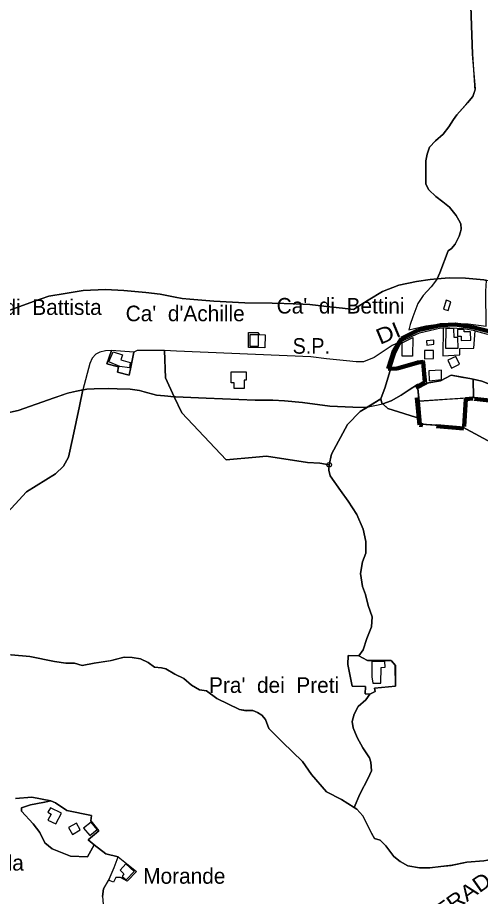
# Model space of a CAD drawing. Extents: x 645880 to 658994, y 884400 to 894744.
# Drawn here: x 655242 to 655748, y 891174 to 892132 of the extents above; entities that cross this region are included whole.
import ezdxf
from ezdxf.enums import TextEntityAlignment as Align

# ---------------------------------------------------------------- set-up
doc = ezdxf.new("R2010")
doc.units = 0
doc.header["$LTSCALE"] = 10
doc.header["$PDMODE"] = 32
doc.header["$PDSIZE"] = 5
doc.linetypes.add('MEDIUM_DASHED', pattern=[4.5, 3, -1.5])
for name, color, linetype, lineweight in [('15', 7, 'MEDIUM_DASHED', 100), ('16', 7, 'Continuous', 25), ('17', 7, 'Continuous', 25), ('2', 7, 'Continuous', 25), ('23', 7, 'Continuous', 25), ('3', 7, 'Continuous', 25), ('30', 7, 'Continuous', 25), ('4', 7, 'Continuous', 25), ('55', 7, 'Continuous', 25), ('6', 7, 'Continuous', 25), ('7', 7, 'Continuous', 25), ('8', 7, 'Continuous', 25)]:
    doc.layers.add(name, color=color, linetype=linetype, lineweight=lineweight)
doc.layers.add('60', color=7, linetype='Continuous')

msp = doc.modelspace()

# ---------------------------------------------------------------- linework, layer by layer
at = {"layer": '15'}
msp.add_lwpolyline([(655646.84, 891749.19), (655653.39, 891769.57), (655661.39, 891782.31), (655679.57, 891791.4), (655703.94, 891796.86), (655720.3, 891797.59), (655740.3, 891794.31), (655765.03, 891788.13), (655784.67, 891779.76), (655812.67, 891765.57), (655817.4, 891761.2), (655803.58, 891742.28), (655790.49, 891748.1), (655785.39, 891736.82), (655770.85, 891713.17), (655739.46, 891716.66), (655731.59, 891716.04), (655729.52, 891684.15), (655680.88, 891688.08), (655676.95, 891728.68), (655687.01, 891734.77), (655685.02, 891756.84), (655679.49, 891755.99), (655656.66, 891749.56)], close=True, dxfattribs=at)
at = {"layer": '16'}
msp.add_line((655300.01, 891217.5), (655279.88, 891225.51), dxfattribs=at)
for points in [[(655719.97, 891885.05), (655724.25, 891894.07), (655725.76, 891898.52), (655726.49, 891901.45), (655726, 891907.49), (655724.13, 891911.49), (655721.15, 891916.55), (655713.8, 891925.74), (655706.51, 891931.31), (655699.02, 891937.11), (655691.32, 891944.32), (655687.8, 891950.52), (655687.83, 891964.63), (655687.99, 891975.96), (655689.38, 891983.24), (655692.1, 891990.88), (655698.55, 891998.12), (655706.76, 892005.17), (655713.02, 892013.38), (655718.06, 892021.09), (655721.68, 892026.19), (655731.7, 892037.05), (655739.31, 892046.15), (655742.28, 892054.6), (655738.97, 892092.57), (655735.1, 892197.24)], [(655700.24, 891847.42), (655703.33, 891853.75), (655712.44, 891877.79), (655715.97, 891880.48), (655719.97, 891885.05)], [(655430.37, 891825.09), (655456.38, 891823.01), (655490.4, 891821.27), (655520.05, 891820.67), (655546.19, 891820.04), (655561.35, 891819.34), (655579.49, 891817.36), (655597.12, 891815.5), (655608.99, 891814.04), (655625.11, 891824.07), (655640.55, 891833.67), (655658.39, 891840.35), (655677.77, 891844.48), (655692.81, 891846.73), (655700.24, 891847.42)], [(655211.7, 891809.51), (655216.33, 891807.57), (655217.29, 891807.64), (655225.68, 891810.38), (655259.64, 891822.71), (655276.25, 891828.39), (655294.18, 891831.5), (655313.72, 891834.83), (655338.39, 891835.61), (655358.19, 891834.55), (655382.34, 891832.59), (655397.87, 891830.69), (655414.28, 891827.27), (655421.79, 891825.76), (655430.37, 891825.09)], [(655313.68, 891726.31), (655306.52, 891724.88), (655296.98, 891722.55), (655282.1, 891717.68), (655262.64, 891710.49), (655243.09, 891703.85), (655222.58, 891699.52), (655203.07, 891700.27), (655188.79, 891704), (655176.07, 891708.49), (655154.59, 891711.51)], [(655297.92, 891652.75), (655302.53, 891674.41), (655309.86, 891708.34), (655313.68, 891726.31)], [(655283.75, 891634.73), (655292.31, 891643.02), (655297.92, 891652.75)], [(655194.14, 891553.82), (655210.59, 891570.1), (655252.01, 891614.96), (655283.75, 891634.73)], [(655391.83, 891423.6), (655384.78, 891428.82), (655376.63, 891432.72), (655367.52, 891434.25), (655358.55, 891434.64), (655343.5, 891430.6), (655325.73, 891428.16), (655312.81, 891425.5), (655304.45, 891428.16), (655294.96, 891428.17), (655282.42, 891429.69), (655255.83, 891435.38), (655235.31, 891437.28), (655214.8, 891435.38), (655193.53, 891432.72), (655174.15, 891432.72), (655164.06, 891433.48)], [(655414.12, 891415.93), (655404.18, 891421.83), (655399.53, 891423), (655391.83, 891423.6)], [(655448.41, 891398), (655440.89, 891398.78), (655432.12, 891404.21), (655423.89, 891411.2), (655414.12, 891415.93)], [(655491.32, 891376.42), (655484.52, 891377.35), (655459.68, 891389.38), (655448.41, 891398)], [(655504.28, 891374.24), (655499.16, 891376.26), (655491.32, 891376.42)], [(655531.34, 891342.01), (655525.92, 891347.38), (655516.69, 891356.69), (655512.89, 891366.48), (655508.86, 891371.37), (655504.28, 891374.24)], [(655579.68, 891287.83), (655563.31, 891306.62), (655553.3, 891320.75), (655531.34, 891342.01)], [(655609.62, 891270.6), (655595.82, 891279.36), (655579.68, 891287.83)], [(655239.85, 891280.32), (655257.81, 891281.71), (655278.73, 891277.92), (655283.76, 891275.63), (655296.11, 891267.39), (655323.1, 891261.67), (655322.41, 891256.18), (655330.87, 891244.96), (655319.21, 891235.35), (655326.07, 891229.86)], [(655270.05, 891275.86), (655278.72, 891277.92), (655257.82, 891281.71), (655239.85, 891280.33)], [(655259.3, 891252.74), (655246.5, 891266.47), (655246.5, 891270.37), (655256.32, 891273.34), (655270.04, 891275.86)], [(655628.81, 891242.58), (655619.19, 891261.38), (655612.5, 891268.62), (655609.62, 891270.6)], [(655279.87, 891225.51), (655272.1, 891232.14), (655266.61, 891243.36), (655259.29, 891252.74)], [(655637.97, 891234.79), (655632.11, 891236.8), (655628.81, 891242.58)], [(655338.47, 891220.11), (655326.07, 891229.86), (655318.75, 891216.81), (655300, 891217.5)], [(655326.07, 891229.86), (655338.47, 891220.11), (655351.99, 891216.87), (655372.17, 891200.77), (655361.89, 891190.13), (655354.57, 891194.25), (655349.54, 891194.25), (655346.89, 891188.94), (655341.73, 891191.31), (655336.12, 891181.8), (655334.94, 891173.54), (655336.12, 891160.58), (655344.36, 891137.59), (655349.67, 891128.75), (655363.8, 891116.96), (655409.75, 891081.01), (655446.27, 891055.66), (655452.99, 891050.47)], [(655652.91, 891217.19), (655644.3, 891228.65), (655637.97, 891234.79)], [(655341.74, 891191.31), (655343.54, 891194.79), (655347.76, 891205.05), (655352, 891216.87), (655338.48, 891220.11)], [(655704.46, 891206.35), (655692.21, 891204.64), (655680.94, 891204.83), (655668.3, 891207.03), (655659.96, 891211.61), (655652.91, 891217.19)], [(655767.1, 891216.28), (655759.41, 891213.88), (655751.17, 891212.3), (655732.6, 891210.97), (655716.83, 891207.52), (655704.46, 891206.35)], [(655334.94, 891173.55), (655336.12, 891181.8), (655341.73, 891191.31)]]:
    msp.add_lwpolyline(points, dxfattribs=at)
at = {"layer": '17'}
msp.add_line((655413.39, 891718.75), (655402.51, 891719.63), dxfattribs=at)
for points in [[(655735.1, 892197.24), (655738.97, 892092.57), (655741.43, 892053.04), (655739.31, 892046.15), (655733.52, 892039.49), (655721.68, 892026.19), (655718.06, 892021.09), (655713.02, 892013.38), (655706.76, 892005.17), (655698.55, 891998.12), (655692.1, 891990.88), (655689.38, 891983.24), (655687.99, 891975.96), (655687.83, 891964.63), (655687.8, 891950.52), (655691.32, 891944.32), (655699.02, 891937.11), (655706.51, 891931.31), (655713.8, 891925.74), (655721.15, 891916.55), (655724.13, 891911.49), (655726, 891907.49), (655726.49, 891901.45), (655725.76, 891898.52), (655724.25, 891894.07), (655719.97, 891885.05)], [(655719.97, 891885.05), (655715.97, 891880.48), (655712.44, 891877.79), (655703.33, 891853.75), (655700.24, 891847.42)], [(655700.24, 891847.42), (655699.56, 891846.42), (655693.7, 891838.71), (655685.03, 891829.36), (655679.08, 891820.43), (655673.63, 891805.75), (655670.94, 891797.41), (655669.46, 891791.77), (655687.95, 891796.1)], [(655687.95, 891796.1), (655704.64, 891798.15), (655718.02, 891798.89), (655734.15, 891798.14), (655753.71, 891795.7), (655753.43, 891833.77), (655754.3, 891845.65)], [(655754.3, 891845.65), (655751.28, 891846.27), (655731.29, 891848.24), (655713.48, 891848.65), (655700.24, 891847.42)], [(655700.24, 891847.42), (655713.48, 891848.65), (655731.29, 891848.24), (655751.28, 891846.27), (655754.3, 891845.65)], [(655332.2, 891767.4), (655327.83, 891765.06), (655323.76, 891760.85)], [(655344.78, 891769.09), (655338.31, 891768.88), (655332.2, 891767.4)], [(655402.54, 891769.12), (655372.88, 891769.05), (655369.38, 891767.53), (655366.07, 891751.07), (655364.09, 891742.17), (655351.2, 891745.67), (655352.51, 891751.29), (655339.9, 891754.79), (655344.78, 891769.09)], [(655365.21, 891726.83), (655375.48, 891725.71), (655380.51, 891724.2), (655394.07, 891720.32), (655402.51, 891719.63), (655413.39, 891718.75), (655403.75, 891739.36), (655402.54, 891769.12)], [(655323.76, 891760.85), (655321.18, 891754.91), (655313.68, 891726.31)], [(655313.68, 891726.31), (655309.86, 891708.34), (655302.53, 891674.41), (655297.92, 891652.75), (655292.31, 891643.02)], [(655313.68, 891726.31), (655317.92, 891727.16), (655325.85, 891727.35), (655341.68, 891727.63), (655350.84, 891727.32), (655365.21, 891726.83)], [(655350.84, 891727.32), (655341.68, 891727.63), (655325.85, 891727.35), (655317.92, 891727.16), (655313.68, 891726.31)], [(655402.51, 891719.63), (655394.07, 891720.32), (655380.51, 891724.2), (655375.48, 891725.71), (655365.21, 891726.83), (655350.84, 891727.32)], [(655626.69, 891394.4), (655621.86, 891394.56), (655622.09, 891402.57), (655607.46, 891402.8), (655602.74, 891426.47), (655603.19, 891436.45), (655614.99, 891436), (655619.73, 891442.67), (655623.59, 891454.9), (655628.74, 891467.78), (655629.38, 891478.72), (655624.88, 891490.95), (655621.98, 891502.86), (655618.76, 891511.87), (655616.83, 891525.71), (655618.76, 891538.59), (655622.3, 891547.92), (655622.62, 891560.8), (655619.73, 891574.32), (655612.65, 891590.41), (655603.32, 891604.9), (655594.96, 891616.49), (655583.7, 891632.26), (655582.09, 891638.7), (655582.42, 891644.49), (655572.43, 891646.12), (655558.88, 891647.07), (655513.97, 891654.03), (655502.53, 891652.82), (655469.89, 891649.98), (655421.64, 891701.11), (655413.39, 891718.75)], [(655682.98, 891688.96), (655682.43, 891694.65), (655646.33, 891705.74), (655640.11, 891711.82), (655638.75, 891716.34), (655616.37, 891702.58), (655602.35, 891688.57), (655585.17, 891656.03)], [(655786.39, 891654.24), (655728.52, 891685.4), (655700.38, 891687.6), (655682.98, 891688.96)], [(655585.17, 891656.03), (655585.17, 891656.03), (655582.42, 891644.49)], [(655292.31, 891643.02), (655283.75, 891634.73), (655252.01, 891614.96)], [(655582.42, 891644.49), (655582.09, 891638.7), (655583.7, 891632.26), (655594.96, 891616.49), (655603.32, 891604.9), (655612.65, 891590.41), (655619.73, 891574.32), (655622.62, 891560.8), (655622.3, 891547.92), (655618.76, 891538.59), (655616.83, 891525.71), (655618.76, 891511.87), (655621.98, 891502.86), (655624.88, 891490.95), (655629.38, 891478.72), (655628.74, 891467.78), (655623.59, 891454.9), (655619.73, 891442.67), (655614.99, 891436)], [(655252.01, 891614.96), (655210.59, 891570.1), (655194.14, 891553.82)], [(655235.32, 891437.29), (655255.83, 891435.39), (655282.42, 891429.69), (655294.96, 891428.17), (655304.46, 891428.17), (655312.81, 891425.5), (655325.73, 891428.17), (655344.34, 891430.83), (655358.55, 891434.64), (655367.52, 891434.25), (655376.63, 891432.72), (655384.78, 891428.82), (655391.83, 891423.6), (655399.53, 891423), (655404.18, 891421.83), (655414.12, 891415.93)], [(655614.99, 891436), (655624.14, 891431.04), (655650.67, 891430.71), (655655.02, 891425.45), (655655.02, 891403.03), (655632.03, 891400.59), (655632.49, 891396.98), (655628.32, 891394.85), (655626.69, 891394.4)], [(655414.12, 891415.93), (655423.89, 891411.2), (655432.12, 891404.21), (655440.89, 891398.78), (655448.41, 891398), (655459.68, 891389.38)], [(655459.68, 891389.38), (655484.52, 891377.35), (655491.97, 891376.1), (655499.16, 891376.26), (655504.28, 891374.24)], [(655609.62, 891270.6), (655615.87, 891285.26), (655624.88, 891302.65), (655628.74, 891310.69), (655628.09, 891320.03), (655626.49, 891324.85), (655619.09, 891335.8), (655612.98, 891347.06), (655608.79, 891357.37), (655607.51, 891364.45), (655609.76, 891372.5), (655614.26, 891380.87), (655622.3, 891387.95), (655626.69, 891394.4)], [(655626.69, 891394.4), (655622.3, 891387.95), (655614.26, 891380.87), (655609.76, 891372.5), (655607.51, 891364.45), (655608.79, 891357.37), (655612.98, 891347.06), (655619.09, 891335.8), (655626.49, 891324.85), (655628.09, 891320.03), (655628.74, 891310.69), (655624.88, 891302.65), (655615.87, 891285.26), (655609.62, 891270.6)], [(655504.28, 891374.24), (655508.86, 891371.37), (655512.89, 891366.48), (655516.69, 891356.69), (655531.34, 891342.01), (655553.3, 891320.75)], [(655553.3, 891320.75), (655563.31, 891306.62), (655579.68, 891287.83)], [(655579.68, 891287.83), (655595.82, 891279.36), (655609.62, 891270.6)], [(655609.62, 891270.6), (655612.5, 891268.62), (655619.19, 891261.38), (655628.81, 891242.58), (655632.11, 891236.8), (655637.97, 891234.79), (655644.3, 891228.65), (655652.91, 891217.19), (655659.96, 891211.61), (655668.3, 891207.03), (655680.94, 891204.83)], [(655680.94, 891204.83), (655692.21, 891204.64), (655704.46, 891206.35), (655715.79, 891207.43), (655732.6, 891210.97), (655751.18, 891212.3), (655759.41, 891213.88)]]:
    msp.add_lwpolyline(points, dxfattribs=at)
msp.add_point((655582.42, 891644.49), dxfattribs=at)
at = {"layer": '2'}
for points in [[(655346.72, 891767.62), (655356.68, 891764.44), (655355.16, 891758.9), (655365.26, 891756.27), (655364.57, 891750.32), (655353.92, 891751.85), (655342.02, 891756.69)], [(655259.29, 891252.74), (655266.61, 891243.36), (655272.1, 891232.14), (655279.87, 891225.51), (655300, 891217.5), (655318.75, 891216.81), (655326.07, 891229.86), (655319.21, 891235.35), (655330.87, 891244.96), (655322.41, 891256.18), (655323.1, 891261.67), (655296.11, 891267.39), (655283.76, 891275.63), (655278.73, 891277.92), (655270.04, 891275.86), (655256.32, 891273.34), (655246.49, 891270.37), (655246.49, 891266.47)], [(655278.11, 891270.03), (655275.42, 891265.54), (655279, 891263.15), (655275.42, 891256.57), (655284.18, 891252.86), (655290.3, 891264.21)], [(655314.08, 891248.17), (655321.11, 891240.01), (655329.26, 891246.56), (655322.5, 891254.71)], [(655297.86, 891248.78), (655302.08, 891241.21), (655310.66, 891246.03), (655306.74, 891253.58)]]:
    msp.add_lwpolyline(points, close=True, dxfattribs=at)
at = {"layer": '23'}
msp.add_lwpolyline([(655680.56, 891714.07), (655682.98, 891688.96), (655728.52, 891685.4), (655730.87, 891717.2)], close=True, dxfattribs=at)
at = {"layer": '3'}
for points in [[(655602.74, 891426.47), (655607.46, 891402.8), (655622.09, 891402.57), (655621.86, 891394.56), (655626.69, 891394.4), (655628.32, 891394.85), (655632.49, 891396.98), (655632.03, 891400.59), (655654.99, 891403.07), (655654.47, 891425.7), (655650.12, 891430.96), (655623.59, 891431.29), (655614.99, 891436), (655603.19, 891436.45)], [(655629.07, 891429.96), (655629.15, 891413.04), (655629.98, 891406.28), (655638.79, 891406.16), (655639.38, 891423.45), (655643.55, 891423.56), (655643.3, 891429.96)]]:
    msp.add_lwpolyline(points, close=True, dxfattribs=at)
at = {"layer": '30'}
msp.add_line((655640.98, 891710.97), (655641.05, 891711.03), dxfattribs=at)
for points in [[(655624.23, 891707.41), (655638.75, 891716.34), (655643.58, 891729.3), (655649.69, 891749.91), (655649.69, 891749.91), (655654.92, 891765.7), (655659.31, 891774.47), (655662.32, 891779.79), (655651.25, 891774.53), (655631.73, 891761.54), (655620.08, 891756.78), (655611.93, 891756.78), (655601.23, 891757.96), (655579.7, 891760.18), (655562.48, 891762.4), (655415.63, 891768.33), (655402.54, 891769.12), (655403.75, 891739.36), (655413.39, 891718.75)], [(655689.09, 891733.72), (655686.48, 891757.95), (655678.39, 891757.37), (655671.21, 891754.75), (655659.82, 891751.55), (655649.69, 891749.91), (655643.58, 891729.3), (655638.75, 891716.34), (655640.11, 891711.82), (655640.98, 891710.97), (655641.05, 891711.03)], [(655689.18, 891732.93), (655686.48, 891757.95), (655678.39, 891757.37), (655671.21, 891754.75), (655659.82, 891751.55), (655649.69, 891749.91), (655643.58, 891729.3), (655638.75, 891716.34), (655640.11, 891711.82), (655640.98, 891710.97), (655641.05, 891711.03)], [(655689.18, 891732.93), (655686.48, 891757.95), (655678.39, 891757.37), (655671.21, 891754.75), (655659.82, 891751.55), (655649.69, 891749.91), (655643.58, 891729.3), (655638.75, 891716.34), (655640.11, 891711.82), (655640.98, 891710.97), (655641.05, 891711.03)], [(655689.18, 891732.93), (655686.48, 891757.95), (655678.39, 891757.37), (655671.21, 891754.75), (655659.82, 891751.55), (655649.69, 891749.91), (655643.58, 891729.3), (655638.75, 891716.34), (655640.11, 891711.82), (655640.98, 891710.97)], [(655669.78, 891726.16), (655678.74, 891732.21), (655689.09, 891733.72)], [(655641.05, 891711.03), (655650.1, 891714.15), (655660.98, 891720.45), (655669.78, 891726.16)], [(655641.05, 891711.03), (655650.1, 891714.15), (655660.98, 891720.45), (655669.78, 891726.16)], [(655641.05, 891711.03), (655650.1, 891714.15), (655660.98, 891720.45), (655669.78, 891726.16)], [(655641.05, 891711.03), (655650.1, 891714.15), (655660.98, 891720.45), (655669.78, 891726.16)], [(655669.78, 891726.16), (655660.98, 891720.45), (655650.1, 891714.15), (655641.05, 891711.03)], [(655669.78, 891726.16), (655678.74, 891732.21), (655689.18, 891732.93)], [(655669.78, 891726.16), (655678.74, 891732.21), (655689.18, 891732.93)], [(655669.78, 891726.16), (655678.74, 891732.21), (655689.18, 891732.93)], [(655689.18, 891732.93), (655678.74, 891732.21), (655669.78, 891726.16)], [(655682.43, 891694.65), (655679.25, 891727.7), (655689.18, 891732.88)], [(655413.39, 891718.75), (655414.72, 891718.64), (655448.2, 891717.07), (655501.55, 891714.9), (655520.78, 891714.9), (655533.84, 891714.12), (655553.45, 891712.46), (655583.07, 891708.37), (655608.33, 891707.35), (655621.67, 891706.86), (655624.23, 891707.41)], [(655624.23, 891707.41), (655621.67, 891706.86), (655608.33, 891707.35), (655583.07, 891708.37), (655553.45, 891712.46), (655533.84, 891714.12), (655520.78, 891714.9), (655501.55, 891714.9), (655448.2, 891717.07), (655414.72, 891718.64), (655413.39, 891718.75)], [(655413.39, 891718.75), (655421.64, 891701.11), (655469.89, 891649.98), (655502.53, 891652.82)], [(655775.65, 891723.07), (655770.51, 891714.36), (655739.87, 891717.77), (655730.87, 891717.2), (655728.52, 891685.4)], [(655502.53, 891652.82), (655513.97, 891654.03), (655558.88, 891647.07), (655572.43, 891646.12), (655582.42, 891644.49), (655585.17, 891656.03), (655602.35, 891688.57), (655616.37, 891702.58), (655624.23, 891707.41)], [(655640.98, 891710.97), (655646.33, 891705.74), (655682.43, 891694.65)], [(655728.52, 891685.4), (655786.39, 891654.24), (655851.67, 891610.21)]]:
    msp.add_lwpolyline(points, dxfattribs=at)
at = {"layer": '4'}
for points in [[(655706.87, 891794.07), (655706.6, 891763.54), (655724.96, 891764.4), (655724.96, 891771.27), (655740.41, 891771.81), (655741.93, 891790.72), (655729.26, 891792.82)], [(655709.82, 891793.07), (655709.61, 891771.81), (655723.13, 891771.91), (655723.03, 891783.41), (655718.73, 891783.41), (655718.62, 891792.86)], [(655722.72, 891791.99), (655722.51, 891784.9), (655726.37, 891784.68), (655726.37, 891780.06), (655737.1, 891780.28), (655736.68, 891789.52), (655729.91, 891789.73), (655729.8, 891791.77)], [(655494.52, 891772.43), (655494.52, 891788.95), (655504.43, 891788.95), (655505.98, 891786.52), (655512.42, 891786.33), (655512.22, 891771.93)], [(655495.72, 891786.41), (655495.72, 891773.93), (655505.28, 891773.77), (655505.28, 891786.41)], [(655369.38, 891767.53), (655344.78, 891769.09), (655339.9, 891754.79), (655352.51, 891751.29), (655351.2, 891745.67), (655364.09, 891742.17), (655366.07, 891751.07)], [(655347.75, 891205.05), (655351.99, 891216.87), (655372.17, 891200.77), (655361.89, 891190.13), (655354.57, 891194.25), (655349.54, 891194.25), (655346.89, 891188.94), (655341.73, 891191.31), (655343.53, 891194.79)], [(655360.3, 891209.06), (655354.33, 891202.24), (655358.4, 891198.25), (655356.34, 891195.46), (655360.75, 891191.58), (655369.7, 891200.58)]]:
    msp.add_lwpolyline(points, close=True, dxfattribs=at)
at = {"layer": '55'}
for points in [[(655756.37, 891845.22), (655751.28, 891846.27), (655731.29, 891848.24), (655713.48, 891848.65), (655692.81, 891846.73), (655677.77, 891844.48), (655658.39, 891840.35), (655640.55, 891833.67), (655625.11, 891824.07), (655608.99, 891814.04), (655597.12, 891815.5), (655579.49, 891817.36), (655561.35, 891819.34), (655546.19, 891820.04), (655520.05, 891820.67), (655490.4, 891821.27), (655456.38, 891823.01), (655430.37, 891825.09)], [(655430.37, 891825.09), (655421.79, 891825.76), (655414.28, 891827.27), (655397.87, 891830.69), (655382.34, 891832.59), (655358.19, 891834.55), (655338.39, 891835.61), (655313.72, 891834.83), (655294.18, 891831.5), (655276.25, 891828.39), (655259.64, 891822.71), (655225.68, 891810.38), (655217.29, 891807.64), (655216.33, 891807.57), (655211.7, 891809.51), (655197.61, 891815.96), (655178.26, 891820.85), (655176.92, 891823.92), (655172.61, 891822.04), (655162.45, 891822.71), (655141.49, 891823.51), (655119.5, 891813.85)], [(655669.78, 891726.16), (655678.74, 891732.21), (655689.09, 891733.72)], [(655689.09, 891733.72), (655704.16, 891736.03), (655715.68, 891742.15), (655726.88, 891740.22), (655736.16, 891738.76), (655749.21, 891735.64), (655759.14, 891731.56), (655775.65, 891723.07), (655792.69, 891716.09)], [(655136.14, 891698.5), (655154.59, 891711.51), (655176.07, 891708.49), (655188.79, 891704), (655203.07, 891700.27), (655222.58, 891699.52), (655243.09, 891703.84), (655262.64, 891710.48), (655282.1, 891717.67), (655296.97, 891722.55), (655306.51, 891724.88), (655317.92, 891727.16), (655325.85, 891727.35), (655341.68, 891727.63), (655350.84, 891727.32)], [(655350.84, 891727.32), (655365.21, 891726.83), (655375.48, 891725.71), (655380.51, 891724.2), (655394.07, 891720.32), (655402.51, 891719.63)], [(655402.51, 891719.63), (655414.72, 891718.64), (655448.2, 891717.07), (655501.55, 891714.9), (655520.78, 891714.9), (655533.84, 891714.12), (655553.45, 891712.46), (655583.07, 891708.37), (655608.33, 891707.35), (655621.67, 891706.86), (655641.05, 891711.03), (655650.1, 891714.15), (655660.98, 891720.45), (655669.78, 891726.16)]]:
    msp.add_lwpolyline(points, dxfattribs=at)
at = {"layer": '6'}
for points in [[(655710.04, 891823.96), (655707.13, 891814.38), (655712.47, 891812.76), (655715.38, 891822.34)], [(655489.73, 891727.67), (655478.63, 891727.67), (655478.63, 891733.87), (655475.63, 891733.87), (655475.63, 891745.87), (655491.73, 891745.87), (655491.73, 891736.87), (655489.73, 891736.87)]]:
    msp.add_lwpolyline(points, close=True, dxfattribs=at)
at = {"layer": '7'}
for points in [[(655662.22, 891777.59), (655673.67, 891783.31), (655673.26, 891763.15), (655662.22, 891763.02)], [(655688.55, 891779.57), (655688.94, 891775.13), (655696.85, 891776.04), (655696.65, 891780.29)], [(655686.48, 891769.01), (655686.58, 891760.2), (655696.44, 891760.31), (655696.34, 891769.12)], [(655712.1, 891758.48), (655716.1, 891749.87), (655724.87, 891754.29), (655720.87, 891762.5)], [(655691.07, 891747.08), (655691.45, 891736.23), (655705.17, 891737.67), (655705.06, 891747.68)]]:
    msp.add_lwpolyline(points, close=True, dxfattribs=at)
at = {"layer": '8'}
for points in [[(655689.09, 891733.72), (655686.48, 891757.95), (655678.39, 891757.37), (655671.21, 891754.75), (655659.82, 891751.55), (655649.69, 891749.91), (655654.92, 891765.7), (655659.31, 891774.47), (655662.32, 891779.79), (655672.89, 891784.69), (655681.12, 891788.41), (655692.1, 891791.07), (655704.32, 891793.8), (655706.87, 891793.83), (655706.6, 891763.54), (655724.96, 891764.4), (655724.96, 891771.27), (655740.41, 891771.81), (655741.93, 891790.72)], [(655741.93, 891790.72), (655753.95, 891787.46), (655762.51, 891785.57), (655776.06, 891780.58), (655789.08, 891774.49), (655797.07, 891770.45), (655810.53, 891764.01), (655810.51, 891764.06), (655814.94, 891760.42), (655802.95, 891743.58), (655790.52, 891750.05), (655787.92, 891743.85), (655775.65, 891723.07)], [(655689.09, 891733.72), (655689.18, 891732.88), (655679.25, 891727.7), (655680.56, 891714.07), (655711.36, 891715.99)], [(655775.65, 891723.07), (655772.99, 891724.28), (655759.14, 891731.56), (655749.21, 891735.64), (655736.16, 891738.76), (655723.85, 891740.81), (655715.68, 891742.15), (655704.16, 891736.03), (655690.82, 891733.84), (655689.09, 891733.72)], [(655739.55, 891737.95), (655736.16, 891738.76), (655723.85, 891740.81), (655715.68, 891742.15), (655704.16, 891736.03), (655690.82, 891733.84), (655689.09, 891733.72)], [(655711.36, 891715.99), (655739.87, 891717.77), (655739.55, 891737.95)], [(655775.65, 891723.07), (655772.99, 891724.28), (655759.14, 891731.56), (655749.21, 891735.64), (655739.55, 891737.95), (655739.87, 891717.77)], [(655739.87, 891717.77), (655770.51, 891714.36), (655775.65, 891723.07)]]:
    msp.add_lwpolyline(points, dxfattribs=at)

# ---------------------------------------------------------------- texts
at = {"layer": '60'}
for s, p in [("Ca'  di  Battista", (655258.07, 891807.99)), ("Ca'  di  Bettini", (655594.91, 891809.51)), ("Ca'  d'Achille", (655425.3, 891801.12)), ("Pra'  dei  Preti", (655522.33, 891395.65)), ('Albaiola', (655208.67, 891201.71)), ('Morande', (655424.31, 891187.39))]:
    msp.add_text(s, height=17, dxfattribs=at).set_placement(p, align=Align.CENTER)
for s, rotation, width, p in [('DI', 22.527, 1.15, (655650.07, 891780.33)), ('STRADA', 35.368, 1.1, (655733.4, 891167.59))]:
    msp.add_text(s, height=17, rotation=rotation, dxfattribs=dict(at, width=width)).set_placement(p, align=Align.CENTER)
at = {"layer": '60', "width": 0.95}
msp.add_text('S.P.', height=17, dxfattribs=at).set_placement((655562.94, 891765.68), align=Align.CENTER)

doc.saveas('drawing.dxf')
